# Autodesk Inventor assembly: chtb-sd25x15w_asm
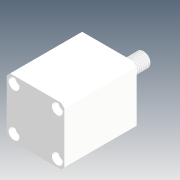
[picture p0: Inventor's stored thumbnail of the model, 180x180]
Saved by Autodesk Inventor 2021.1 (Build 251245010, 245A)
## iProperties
Company: Microsoft
Created: 2018-05
Part Number: chtb-sd25x15w_asm
Description: STEP AP214
Document SubType Name: Assembly
Designer: user
Title: chtb-sd25x15w_asm.STEP
Author: Windows
Revision Number: ÈÎºÎ
Sending System: SolidWorks 2015
Preprocessor: SwSTEP 2.0
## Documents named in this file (4)
- D:\Vault_2016\Projekty\Clamptek\Hydraulic\CHTB\CHTB-25\Inventor\chtb-sd25x15w\chtb-sd25x15w_asm.iam
- D:\Vault_2016\Projekty\Clamptek\Hydraulic\CHTB\CHTB-25\Inventor\chtb-sd25x15w\CHTB-25QG.ipt
- D:\Vault_2016\Projekty\Clamptek\Hydraulic\CHTB\CHTB-25\Inventor\chtb-sd25x15w\CHTB-SD15X15WHSG.ipt
- D:\Vault_2016\Projekty\Clamptek\Hydraulic\CHTB\CHTB-25\Inventor\chtb-sd25x15w\CHTB-SD25X15NBT.ipt
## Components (3 placed, 3 different names)
1. CHTB-25QG_1
2. CHTB-SD15X15WHSG_2
3. CHTB-SD25X15NBT_3
